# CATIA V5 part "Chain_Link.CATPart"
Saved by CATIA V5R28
Part number: Chain_Link
Bounding box of the stored display mesh (mm): x -64.818 to 105, y -30 to 30, z -30 to 30
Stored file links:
  E:\Back up\Mission d'enseignement\TP Catia\2 oct - Assemblage\Chain_Link.CATPart
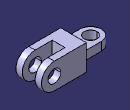
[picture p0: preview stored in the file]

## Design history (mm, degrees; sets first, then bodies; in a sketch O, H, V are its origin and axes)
Body1 (main body)
  Sketch1 on xy-plane, origin (0, 0, 0), H (1, 0, 0), V (0, 1, 0)
    point P1 (-30, 0)
    line L1 (0, 25) -> (0, -25)
    line L2 (0, -25) -> (-40.0001, -25)
    line L3 (-39.9999, 25) -> (0, 25)
    point P2 (0, 25)
    point P4 (-60, 20)
    arc A1 centre (-40, 0) radius 25 from (-39.9999, 25) to (-40.0001, -25) ccw
    point P5 (-40, 0)
    point P6 (-65, 0)
    length L1 = 50
    radius A1 = 25
    distance P5 L1 = 40
    coincidence: P1 H, P2 V, P5 H, A1 P6
    vertical: L1 V
    horizontal: L2 H, L3 H
    equidistance: L2 L3 P1
  Pad1: profile Sketch1, direction (0, 0, 1), length 10, mirrored extent
  Sketch2 on zx-plane, origin (0, 0, 0), H (-1, 0, 0), V (0, 0, 1)
    point P1 (-50, 0)
    line L1 (0, 30) -> (0, -30)
    line L2 (0, -30) -> (-75, -30)
    line L3 (-75, 30) -> (0, 30)
    point P4 (-100, 25)
    arc A1 centre (-75, 0) radius 30 from (-75, 30) to (-75, -30) ccw
    point P5 (-75, 0)
    point P6 (-100, 0)
    length L1 = 60
    distance P5 L1 = 75
    coincidence: P1 H, V L1
    vertical: L1 V
    horizontal: L2 H, L3 H
    equidistance: L2 L3 P1
    tangency: A1 L2, A1 L3
  Pad2: profile Sketch2, direction (0, 1, 0), length 30, mirrored extent
  Sketch3 on xy-plane, origin (0, 0, 0), H (-1, 0, 0), V (0, -1, 0)
    line L1 (-35, 15) -> (-35, -15)
    line L2 (-35, -15) -> (-105, -15)
    line L3 (-105, 15) -> (-35, 15)
    point P1 (-35, 15)
    point P2 (-35, -15)
    reference projected point E1 (0, -30) from edge [face of Pad2 from Sketch2.L1 | end face of Pad2]
    line L4 (-105, 15) -> (-105, -15)
    distance L1 E1 = 35
    distance L3 L2 = 30
    length L3 = 70
    vertical: L1 V, L4 V
    horizontal: L2 H, L3 H
    symmetry: P1 P2 H
  Pocket1: profile Sketch3, direction (0, 0, -1), length 30, mirrored extent
  Sketch4 on start face of Pad2, origin (0, -30, 0), H (1, 0, 0), V (0, 0, 1)
    circle A1 centre (75, 0) radius 15
    point P1 (75, 0)
    reference projected arc E1 centre (75, 0) radius 30 from (75, -30) to (75, 30) ccw from edge [start face of Pad2 | face of Pad2 from Sketch2.A1]
    radius A1 = 15
    coincidence: P1 H
    concentricity: A1 E1
  Pocket2: profile Sketch4, direction (0, 1, 0), through (limit type 3)
  Sketch5 on end face of Pad1, origin (0, 0, 10), H (1, 0, 0), V (0, 1, 0)
    circle A1 centre (-40, 0) radius 15
    point P1 (-40, 0)
    reference projected arc E1 centre (-40, 0) radius 25 from (-39.9999, 25) to (-40.0001, -25) ccw from edge [face of Pad1 from Sketch1.A1 | end face of Pad1]
    radius A1 = 15
    coincidence: P1 H
    concentricity: A1 E1
  Pocket3: profile Sketch5, direction (0, 0, -1), through (limit type 3)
